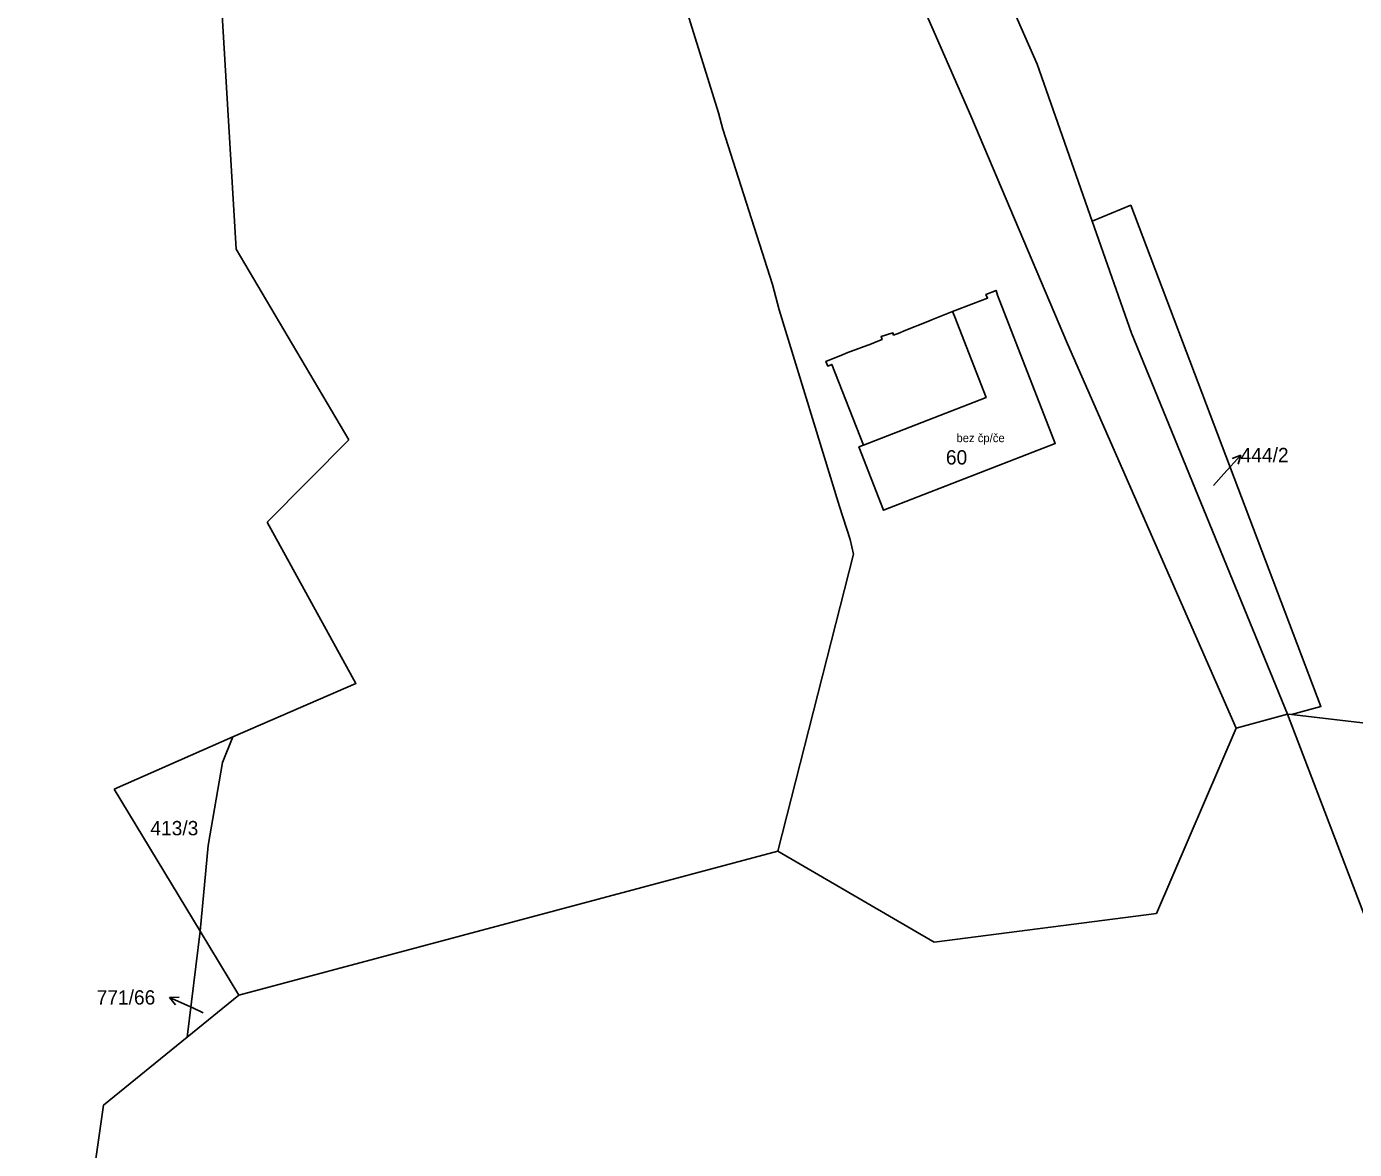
# Model space of a CAD drawing. Extents: x -887272 to -877616, y -1026687 to -1019819.
# Drawn here: x -880227.1 to -880069.6, y -1023116.9 to -1022983.7 of the extents above; entities that cross this region are included whole.
import ezdxf

# ---------------------------------------------------------------- set-up
doc = ezdxf.new("R2010")
doc.units = 0
for name, color, linetype in [('Definiční body', 7, 'Continuous'), ('Hranice parcel', 7, 'Continuous'), ('Parcelní čísla', 7, 'Continuous'), ('Polygon budovy', 7, 'Continuous'), ('Pop  PČ popisy', 7, 'Continuous'), ('Vnitřní kresba', 7, 'Continuous')]:
    doc.layers.add(name, color=color, linetype=linetype)

msp = doc.modelspace()

# ---------------------------------------------------------------- linework, layer by layer
at = {"layer": 'Hranice parcel'}
for p, q in [((-880198.56, -1023042.48), (-880188.9, -1023032.74)), ((-880198.56, -1023042.48), (-880188.9, -1023032.74)), ((-880138, -1023081.51), (-880129.04, -1023046.29)), ((-880083.68, -1023066.92), (-880077.59, -1023065.26)), ((-880077.59, -1023065.26), (-880077.12, -1023065.31)), ((-880093.11, -1023088.89), (-880083.68, -1023066.92)), ((-880216.7, -1023074.16), (-880202.65, -1023067.93)), ((-880216.7, -1023074.16), (-880202.65, -1023067.93)), ((-880206.52, -1023090.97), (-880216.7, -1023074.16)), ((-880206.52, -1023090.97), (-880216.7, -1023074.16)), ((-880201.92, -1023098.58), (-880138, -1023081.51)), ((-880208.05, -1023103.56), (-880206.52, -1023090.97)), ((-880206.52, -1023090.97), (-880201.92, -1023098.58)), ((-880206.52, -1023090.97), (-880201.92, -1023098.58)), ((-880201.92, -1023098.58), (-880208.05, -1023103.56))]:
    msp.add_line(p, q, dxfattribs=at)
for points in [[(-880189.68, -1022867.94), (-880186.63, -1022866.58), (-880188.91, -1022861.28), (-880180.55, -1022856.51), (-880188.62, -1022834.25), (-880191.78, -1022835.57), (-880191.23, -1022832.04), (-880189.34, -1022824.54), (-880188.21, -1022820.18), (-880182.52, -1022840.37), (-880174.52, -1022862.04), (-880144.98, -1022926.17), (-880115.13, -1022994.32), (-880103.69, -1023021.35), (-880083.68, -1023066.92)], [(-880129.04, -1023046.29), (-880129.43, -1023044.54), (-880130.69, -1023040.62), (-880137.84, -1023017.32), (-880138.66, -1023014.32), (-880144.53, -1022995.91), (-880145.04, -1022993.98), (-880153.89, -1022965.48), (-880164.21, -1022937.78), (-880165.13, -1022937.04), (-880174.46, -1022929.37), (-880190.85, -1022916.02), (-880200.32, -1022903.66)], [(-880100.73, -1023006.79), (-880107.25, -1022988.21), (-880135.5, -1022924.1)], [(-880188.9, -1023032.74), (-880202.24, -1023010.12), (-880204.04, -1022980.32)], [(-880188.9, -1023032.74), (-880202.24, -1023010.12), (-880204.04, -1022980.32)], [(-880100.73, -1023006.79), (-880096.17, -1023004.93), (-880073.63, -1023064.34), (-880077.12, -1023065.31)], [(-880077.59, -1023065.26), (-880096.07, -1023020.09), (-880100.73, -1023006.79)], [(-880113.14, -1023015.95), (-880117.31, -1023017.53), (-880119.68, -1023018.48), (-880120.22, -1023018.71), (-880123.03, -1023019.81), (-880123.57, -1023020.04), (-880124.29, -1023020.31), (-880124.38, -1023020.05), (-880125.77, -1023020.5), (-880125.65, -1023020.83), (-880126.37, -1023021.1), (-880126.93, -1023021.35), (-880129.73, -1023022.37), (-880130.28, -1023022.62), (-880132.31, -1023023.43), (-880132.09, -1023023.99), (-880131.63, -1023023.8), (-880127.85, -1023033.36), (-880128.4, -1023033.58), (-880125.5, -1023041.09), (-880105.12, -1023033.15), (-880111.96, -1023015.59), (-880112.13, -1023015.01), (-880113.34, -1023015.51), (-880113.14, -1023015.95)], [(-880202.65, -1023067.93), (-880188.04, -1023061.62), (-880198.56, -1023042.48)], [(-880202.65, -1023067.93), (-880188.04, -1023061.62), (-880198.56, -1023042.48)], [(-880009.23, -1023276.92), (-880020.51, -1023239.61), (-880038.19, -1023176.27), (-880058.64, -1023114.79), (-880077.59, -1023065.26)], [(-880077.12, -1023065.31), (-880055.22, -1023067.87), (-880041.66, -1023106.22), (-880029.62, -1023146.23), (-880004.11, -1023215.22), (-879985.57, -1023257.44), (-879802.44, -1023195.78)], [(-880202.65, -1023067.93), (-880203.87, -1023070.99), (-880205.58, -1023080.83), (-880206.52, -1023090.97)], [(-880093.11, -1023088.89), (-880119.5, -1023092.28), (-880138, -1023081.51)], [(-880227.1, -1023175.62), (-880217.96, -1023111.6), (-880208.05, -1023103.56)]]:
    msp.add_lwpolyline(points, dxfattribs=at)
at = {"layer": 'Polygon budovy'}
msp.add_lwpolyline([(-880127.85, -1023033.36), (-880128.4, -1023033.58), (-880125.5, -1023041.09), (-880105.12, -1023033.15), (-880111.96, -1023015.59), (-880112.13, -1023015.01), (-880113.34, -1023015.51), (-880113.14, -1023015.95), (-880117.31, -1023017.53), (-880117.05, -1023018.07), (-880113.33, -1023027.7)], close=True, dxfattribs=at)
at = {"layer": 'Pop  PČ popisy'}
for p, q in [((-880085.13, -1023036.78), (-880083.12, -1023034.55)), ((-880083.12, -1023034.55), (-880084.16, -1023034.96)), ((-880083.12, -1023034.55), (-880083.42, -1023035.63)), ((-880086.35, -1023038.15), (-880085.13, -1023036.78)), ((-880210.14, -1023098.86), (-880209.02, -1023098.81)), ((-880207.4, -1023100.08), (-880210.14, -1023098.86)), ((-880210.14, -1023098.86), (-880209.43, -1023099.72)), ((-880206.14, -1023100.65), (-880207.4, -1023100.08))]:
    msp.add_line(p, q, dxfattribs=at)
at = {"layer": 'Vnitřní kresba'}
for p, q in [((-880117.31, -1023017.53), (-880117.05, -1023018.07)), ((-880117.05, -1023018.07), (-880113.33, -1023027.7)), ((-880127.85, -1023033.36), (-880113.33, -1023027.7))]:
    msp.add_line(p, q, dxfattribs=at)

# ---------------------------------------------------------------- texts
at = {"layer": 'Definiční body'}
msp.add_text('bez čp/če', height=1, dxfattribs=at).set_placement((-880116.84, -1023033.01))
at = {"layer": 'Parcelní čísla'}
for s, p in [('60', (-880118.09, -1023035.66)), ('444/2', (-880083.14, -1023035.39)), ('413/3', (-880212.42, -1023079.62)), ('771/66', (-880218.79, -1023099.69))]:
    msp.add_text(s, height=1.7, dxfattribs=at).set_placement(p)

doc.saveas('drawing.dxf')
